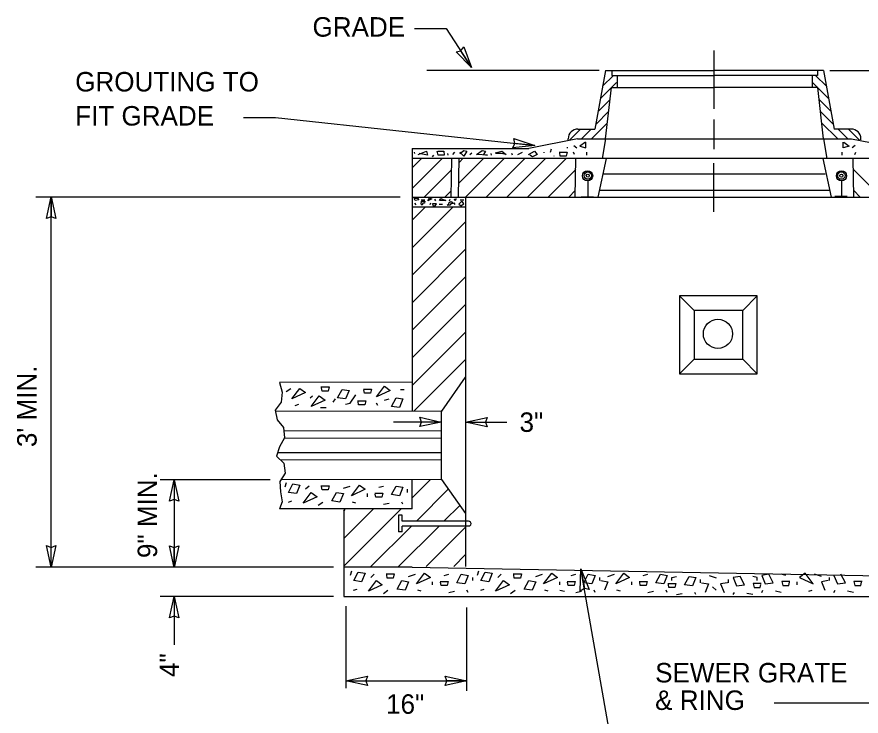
# Model space of a CAD drawing. Extents: x 19188 to 19495, y 20866 to 21061.
# Drawn here: x 19289.27 to 19325.6, y 20943.77 to 20973.85 of the extents above; entities that cross this region are included whole.
import ezdxf

# ---------------------------------------------------------------- set-up
doc = ezdxf.new("R2010")
doc.units = 0
doc.layers.add('G-ANNO-NOTE', color=7, linetype='Continuous')

msp = doc.modelspace()

# ---------------------------------------------------------------- linework, layer by layer
at = {"layer": 'G-ANNO-NOTE'}
for p, q in [((19306.374, 20973.354), (19307.75, 20973.354)), ((19307.75, 20973.354), (19308.836, 20971.674)), ((19308.836, 20971.674), (19308.373, 20972.39)), ((19314.326, 20971.541), (19306.915, 20971.541)), ((19314.6, 20971.541), (19314.141, 20969.028)), ((19314.476, 20970.865), (19314.943, 20971.332)), ((19314.6, 20971.541), (19319.291, 20971.541)), ((19314.867, 20971.541), (19314.867, 20971.332)), ((19314.867, 20971.332), (19319.291, 20971.332)), ((19315.098, 20971.332), (19315.098, 20970.822)), ((19323.983, 20971.541), (19319.291, 20971.541)), ((19323.715, 20971.332), (19319.291, 20971.332)), ((19323.484, 20971.332), (19323.484, 20970.822)), ((19324.107, 20970.865), (19323.639, 20971.332)), ((19323.715, 20971.541), (19323.715, 20971.332)), ((19323.983, 20971.541), (19324.442, 20969.028)), ((19324.256, 20971.541), (19342.735, 20971.541)), ((19314.404, 20970.358), (19315.077, 20971.03)), ((19324.178, 20970.358), (19323.506, 20971.03)), ((19314.6, 20968.603), (19314.855, 20970.808)), ((19314.855, 20970.808), (19319.291, 20970.808)), ((19323.728, 20970.808), (19319.291, 20970.808)), ((19323.983, 20968.603), (19323.728, 20970.808)), ((19314.278, 20969.777), (19314.793, 20970.293)), ((19324.305, 20969.777), (19323.789, 20970.293)), ((19299.023, 20969.523), (19300.399, 20969.523)), ((19300.399, 20969.523), (19311.551, 20968.313)), ((19314.734, 20969.785), (19314.19, 20969.242)), ((19323.849, 20969.785), (19324.392, 20969.242)), ((19314.004, 20968.615), (19314.673, 20969.284)), ((19324.579, 20968.615), (19323.91, 20969.284)), ((19313.054, 20968.554), (19313.528, 20969.028)), ((19313.414, 20969.028), (19314.141, 20969.028)), ((19313.574, 20968.625), (19313.962, 20969.014)), ((19325.169, 20969.028), (19324.442, 20969.028)), ((19325.009, 20968.625), (19324.62, 20969.014)), ((19325.528, 20968.554), (19325.054, 20969.028)), ((19311.551, 20968.313), (19310.704, 20968.405)), ((19313.398, 20968.609), (19311.304, 20968.19)), ((19312.995, 20968.564), (19312.995, 20968.609)), ((19313.398, 20968.609), (19325.184, 20968.609)), ((19314.6, 20968.603), (19314.453, 20967.766)), ((19323.983, 20968.603), (19324.129, 20967.766)), ((19325.184, 20968.609), (19327.279, 20968.19)), ((19325.588, 20968.564), (19325.588, 20968.609)), ((19306.277, 20968.19), (19306.277, 20956.881)), ((19306.277, 20968.19), (19311.304, 20968.19)), ((19306.277, 20967.771), (19332.306, 20967.771)), ((19306.277, 20966.462), (19307.585, 20967.771)), ((19306.277, 20967.351), (19306.697, 20967.771)), ((19307.952, 20966.096), (19307.986, 20967.764)), ((19308.267, 20966.119), (19308.3, 20967.766)), ((19309.363, 20967.771), (19308.294, 20966.703)), ((19308.474, 20967.771), (19308.311, 20967.608)), ((19308.575, 20966.096), (19310.221, 20967.741)), ((19309.464, 20966.096), (19311.116, 20967.747)), ((19312.029, 20967.771), (19310.371, 20966.114)), ((19311.242, 20966.096), (19312.918, 20967.771)), ((19313.295, 20966.096), (19313.328, 20967.771)), ((19314.633, 20967.766), (19314.274, 20966.098)), ((19323.95, 20967.766), (19324.309, 20966.098)), ((19325.288, 20966.096), (19325.254, 20967.771)), ((19312.13, 20966.096), (19313.318, 20967.284)), ((19326.452, 20966.096), (19325.264, 20967.284)), ((19306.798, 20966.096), (19307.965, 20967.262)), ((19314.504, 20967.098), (19324.055, 20967.098)), ((19313.836, 20966.798), (19313.836, 20966.118)), ((19324.747, 20966.798), (19324.747, 20966.118)), ((19307.687, 20966.096), (19307.958, 20966.366)), ((19313.019, 20966.096), (19313.3, 20966.377)), ((19314.376, 20966.39), (19324.252, 20966.39)), ((19319.274, 20966.39), (19319.274, 20966.39)), ((19319.308, 20966.39), (19319.308, 20966.39)), ((19325.563, 20966.096), (19325.282, 20966.377)), ((19305.758, 20966.096), (19290.082, 20966.096)), ((19290.747, 20950.176), (19290.747, 20966.106)), ((19290.747, 20966.106), (19290.747, 20965.254)), ((19306.277, 20966.096), (19332.306, 20966.096)), ((19306.361, 20966.044), (19306.503, 20966.058)), ((19306.402, 20965.948), (19306.361, 20966.044)), ((19306.57, 20965.975), (19306.402, 20965.948)), ((19306.503, 20966.058), (19306.57, 20965.975)), ((19306.663, 20965.797), (19306.688, 20965.921)), ((19306.67, 20965.986), (19306.818, 20965.986)), ((19306.688, 20965.921), (19306.822, 20965.921)), ((19306.738, 20965.838), (19306.712, 20965.756)), ((19306.813, 20965.838), (19306.738, 20965.838)), ((19306.822, 20965.921), (19306.813, 20965.838)), ((19306.948, 20965.934), (19307.023, 20966.058)), ((19307.124, 20966.03), (19306.948, 20965.934)), ((19307.023, 20966.058), (19307.124, 20966.03)), ((19307.451, 20965.948), (19307.518, 20966.044)), ((19307.728, 20965.948), (19307.451, 20965.948)), ((19307.518, 20966.044), (19307.728, 20965.948)), ((19307.862, 20965.811), (19307.87, 20965.866)), ((19307.87, 20965.866), (19307.946, 20965.907)), ((19307.963, 20965.825), (19307.896, 20965.756)), ((19307.946, 20965.907), (19308.022, 20965.88)), ((19308.039, 20965.825), (19307.963, 20965.825)), ((19308.022, 20965.88), (19308.039, 20965.825)), ((19308.105, 20966.016), (19308.173, 20966.03)), ((19308.13, 20965.934), (19308.105, 20966.016)), ((19308.173, 20966.03), (19308.13, 20965.934)), ((19308.424, 20965.921), (19308.29, 20965.797)), ((19308.348, 20965.986), (19308.496, 20965.986)), ((19308.382, 20965.729), (19308.508, 20965.825)), ((19308.508, 20965.825), (19308.424, 20965.921)), ((19308.58, 20966.096), (19308.58, 20950.208)), ((19313.552, 20966.107), (19314.079, 20966.107)), ((19324.997, 20966.118), (19324.47, 20966.118)), ((19306.277, 20965.677), (19308.58, 20965.677)), ((19306.277, 20963.922), (19308.024, 20965.669)), ((19306.277, 20965.107), (19306.822, 20965.652)), ((19306.712, 20965.756), (19306.663, 20965.797)), ((19307.325, 20965.811), (19307.158, 20965.811)), ((19307.158, 20965.811), (19307.174, 20965.742)), ((19307.174, 20965.742), (19307.275, 20965.729)), ((19307.275, 20965.729), (19307.325, 20965.811)), ((19307.442, 20965.794), (19307.59, 20965.794)), ((19307.779, 20965.756), (19307.862, 20965.811)), ((19307.854, 20965.756), (19307.779, 20965.756)), ((19307.896, 20965.756), (19307.854, 20965.756)), ((19308.29, 20965.797), (19308.382, 20965.729)), ((19306.277, 20962.737), (19308.579, 20965.039)), ((19306.277, 20961.552), (19308.577, 20963.852)), ((19306.277, 20960.367), (19308.575, 20962.665)), ((19321.131, 20961.851), (19317.78, 20961.851)), ((19317.78, 20961.851), (19317.78, 20958.499)), ((19317.78, 20961.851), (19318.408, 20961.222)), ((19321.131, 20961.851), (19320.503, 20961.222)), ((19321.131, 20958.499), (19321.131, 20961.851)), ((19306.277, 20959.182), (19308.572, 20961.478)), ((19318.408, 20961.222), (19318.408, 20959.127)), ((19320.503, 20961.222), (19318.408, 20961.222)), ((19320.503, 20959.127), (19320.503, 20961.222)), ((19306.277, 20957.997), (19308.571, 20960.291)), ((19306.346, 20956.881), (19308.568, 20959.104)), ((19318.408, 20959.127), (19317.78, 20958.499)), ((19318.408, 20959.127), (19320.503, 20959.127)), ((19320.503, 20959.127), (19321.131, 20958.499)), ((19308.567, 20958.349), (19307.54, 20956.881)), ((19317.78, 20958.499), (19321.131, 20958.499)), ((19306.277, 20958.136), (19300.565, 20958.127)), ((19300.857, 20957.732), (19301.054, 20957.87)), ((19301.103, 20957.412), (19301.447, 20957.87)), ((19301.447, 20957.87), (19301.694, 20957.686)), ((19303.073, 20957.458), (19303.27, 20957.824)), ((19303.27, 20957.824), (19303.566, 20957.778)), ((19304.748, 20957.504), (19305.092, 20957.961)), ((19305.092, 20957.961), (19305.339, 20957.778)), ((19305.782, 20957.824), (19305.929, 20957.824)), ((19301.694, 20957.686), (19301.103, 20957.412)), ((19301.891, 20957.458), (19301.989, 20957.55)), ((19301.94, 20957.092), (19302.285, 20957.55)), ((19302.285, 20957.55), (19302.531, 20957.366)), ((19303.418, 20957.412), (19303.073, 20957.458)), ((19303.566, 20957.778), (19303.418, 20957.412)), ((19303.615, 20957.229), (19303.861, 20957.595)), ((19305.339, 20957.778), (19304.748, 20957.504)), ((19305.388, 20957.092), (19305.585, 20957.458)), ((19305.585, 20957.458), (19305.88, 20957.412)), ((19301.25, 20957.138), (19301.398, 20957.184)), ((19302.531, 20957.366), (19301.94, 20957.092)), ((19302.876, 20957.275), (19302.975, 20957.412)), ((19303.418, 20957.184), (19303.615, 20957.229)), ((19304.797, 20957.138), (19304.748, 20957.229)), ((19305.092, 20957.366), (19305.29, 20957.412)), ((19305.88, 20957.412), (19305.733, 20957.047)), ((19307.54, 20956.881), (19300.415, 20956.869)), ((19302.334, 20957.047), (19302.581, 20957.047)), ((19305.733, 20957.047), (19305.388, 20957.092)), ((19307.531, 20956.881), (19307.561, 20956.912)), ((19307.533, 20956.881), (19307.533, 20953.949)), ((19307.533, 20956.42), (19305.48, 20956.42)), ((19307.533, 20956.42), (19306.681, 20956.42)), ((19308.58, 20956.42), (19310.36, 20956.42)), ((19308.58, 20956.42), (19309.434, 20956.42)), ((19307.541, 20956.043), (19300.787, 20956.032)), ((19307.519, 20955.729), (19300.787, 20955.718)), ((19307.519, 20955.101), (19300.505, 20955.089)), ((19307.519, 20954.787), (19300.637, 20954.775)), ((19300.167, 20953.937), (19295.44, 20953.937)), ((19296.039, 20953.937), (19296.039, 20950.166)), ((19296.039, 20953.937), (19296.039, 20953.084)), ((19307.545, 20953.949), (19300.638, 20953.937)), ((19306.277, 20952.69), (19306.277, 20953.949)), ((19306.277, 20953.153), (19307.072, 20953.949)), ((19307.545, 20953.949), (19308.577, 20952.484)), ((19300.857, 20953.801), (19300.808, 20953.618)), ((19300.955, 20953.389), (19301.152, 20953.755)), ((19301.152, 20953.755), (19301.447, 20953.709)), ((19301.447, 20953.709), (19301.3, 20953.343)), ((19301.842, 20953.663), (19301.694, 20953.527)), ((19303.319, 20953.572), (19303.615, 20953.663)), ((19303.664, 20953.252), (19304.009, 20953.709)), ((19304.255, 20953.527), (19303.664, 20953.252)), ((19304.009, 20953.709), (19304.255, 20953.527)), ((19304.846, 20953.618), (19305.043, 20953.663)), ((19305.388, 20953.298), (19305.585, 20953.663)), ((19305.585, 20953.663), (19305.88, 20953.618)), ((19305.88, 20953.618), (19305.733, 20953.252)), ((19306.078, 20953.389), (19306.078, 20953.527)), ((19307.834, 20953.526), (19306.482, 20952.174)), ((19301.3, 20953.343), (19300.955, 20953.389)), ((19301.596, 20952.932), (19301.94, 20953.389)), ((19302.186, 20953.206), (19301.596, 20952.932)), ((19301.94, 20953.389), (19302.186, 20953.206)), ((19302.827, 20953.024), (19303.024, 20953.389)), ((19303.024, 20953.389), (19303.319, 20953.343)), ((19303.319, 20953.343), (19303.171, 20952.978)), ((19304.354, 20953.206), (19304.354, 20953.343)), ((19305.733, 20953.252), (19305.388, 20953.298)), ((19300.955, 20952.978), (19301.103, 20953.024)), ((19302.236, 20952.841), (19302.433, 20952.978)), ((19303.171, 20952.978), (19302.827, 20953.024)), ((19303.861, 20952.932), (19303.713, 20952.978)), ((19305.043, 20952.886), (19305.29, 20952.932)), ((19305.88, 20952.886), (19305.831, 20952.978)), ((19308.328, 20952.834), (19307.664, 20952.171)), ((19306.277, 20952.69), (19300.574, 20952.68)), ((19303.344, 20950.22), (19305.807, 20952.683)), ((19303.344, 20951.405), (19304.605, 20952.666)), ((19303.344, 20952.591), (19303.403, 20952.65)), ((19303.344, 20952.649), (19303.344, 20950.176)), ((19305.849, 20952.411), (19305.694, 20952.411)), ((19305.694, 20952.411), (19305.694, 20951.693)), ((19305.849, 20952.156), (19305.849, 20952.411)), ((19308.697, 20952.156), (19305.849, 20952.156)), ((19304.492, 20950.184), (19306.25, 20951.942)), ((19305.684, 20950.191), (19307.426, 20951.932)), ((19305.849, 20951.693), (19305.694, 20951.693)), ((19308.701, 20951.947), (19305.849, 20951.947)), ((19305.849, 20951.693), (19305.849, 20951.947)), ((19306.876, 20950.198), (19308.578, 20951.899)), ((19290.747, 20950.176), (19290.747, 20951.029)), ((19296.039, 20950.166), (19296.039, 20951.018)), ((19308.068, 20950.205), (19308.58, 20950.717)), ((19302.896, 20950.176), (19290.082, 20950.176)), ((19306.277, 20950.176), (19303.344, 20950.176)), ((19303.344, 20950.176), (19303.344, 20948.92)), ((19303.664, 20950.006), (19303.615, 20949.824)), ((19303.763, 20949.595), (19303.959, 20949.961)), ((19303.959, 20949.961), (19304.255, 20949.915)), ((19304.255, 20949.915), (19304.107, 20949.549)), ((19304.649, 20949.869), (19304.501, 20949.732)), ((19306.127, 20949.778), (19306.422, 20949.869)), ((19306.277, 20950.176), (19330.133, 20949.734)), ((19306.471, 20949.458), (19306.816, 20949.915)), ((19306.816, 20949.915), (19307.063, 20949.732)), ((19307.653, 20949.824), (19307.851, 20949.869)), ((19308.195, 20949.504), (19308.392, 20949.869)), ((19308.392, 20949.869), (19308.688, 20949.824)), ((19309.131, 20950.006), (19309.082, 20949.824)), ((19309.229, 20949.595), (19309.426, 20949.961)), ((19309.426, 20949.961), (19309.722, 20949.915)), ((19309.722, 20949.915), (19309.574, 20949.549)), ((19310.116, 20949.869), (19309.968, 20949.732)), ((19311.594, 20949.778), (19311.889, 20949.869)), ((19311.938, 20949.458), (19312.283, 20949.915)), ((19312.283, 20949.915), (19312.53, 20949.732)), ((19313.12, 20949.824), (19313.318, 20949.869)), ((19315.064, 20941.426), (19313.543, 20950.097)), ((19313.543, 20950.097), (19313.691, 20949.257)), ((19313.662, 20949.504), (19313.859, 20949.869)), ((19313.859, 20949.869), (19314.155, 20949.824)), ((19314.697, 20949.778), (19314.992, 20949.869)), ((19315.042, 20949.458), (19315.386, 20949.915)), ((19315.386, 20949.915), (19315.632, 20949.732)), ((19316.224, 20949.824), (19316.42, 20949.869)), ((19316.765, 20949.504), (19316.962, 20949.869)), ((19316.962, 20949.869), (19317.258, 20949.824)), ((19321.621, 20949.869), (19321.325, 20949.824)), ((19321.818, 20949.504), (19321.621, 20949.869)), ((19322.359, 20949.824), (19322.162, 20949.869)), ((19323.196, 20949.915), (19322.95, 20949.732)), ((19323.541, 20949.458), (19323.196, 20949.915)), ((19323.886, 20949.778), (19323.59, 20949.869)), ((19324.92, 20949.504), (19324.723, 20949.869)), ((19304.107, 20949.549), (19303.763, 20949.595)), ((19304.403, 20949.138), (19304.748, 20949.595)), ((19304.748, 20949.595), (19304.994, 20949.412)), ((19305.634, 20949.229), (19305.831, 20949.595)), ((19305.831, 20949.595), (19306.127, 20949.549)), ((19306.127, 20949.549), (19305.979, 20949.184)), ((19307.063, 20949.732), (19306.471, 20949.458)), ((19307.161, 20949.412), (19307.161, 20949.549)), ((19308.54, 20949.458), (19308.195, 20949.504)), ((19308.688, 20949.824), (19308.54, 20949.458)), ((19308.885, 20949.595), (19308.885, 20949.732)), ((19309.574, 20949.549), (19309.229, 20949.595)), ((19309.87, 20949.138), (19310.215, 20949.595)), ((19310.215, 20949.595), (19310.461, 20949.412)), ((19311.101, 20949.229), (19311.298, 20949.595)), ((19311.298, 20949.595), (19311.594, 20949.549)), ((19311.594, 20949.549), (19311.446, 20949.184)), ((19312.53, 20949.732), (19311.938, 20949.458)), ((19312.628, 20949.412), (19312.628, 20949.549)), ((19314.007, 20949.458), (19313.662, 20949.504)), ((19314.155, 20949.824), (19314.007, 20949.458)), ((19314.352, 20949.595), (19314.352, 20949.732)), ((19314.401, 20949.595), (19314.697, 20949.549)), ((19314.697, 20949.549), (19314.549, 20949.184)), ((19315.632, 20949.732), (19315.042, 20949.458)), ((19315.731, 20949.412), (19315.731, 20949.549)), ((19317.11, 20949.458), (19316.765, 20949.504)), ((19317.258, 20949.824), (19317.11, 20949.458)), ((19317.455, 20949.732), (19317.652, 20949.778)), ((19317.455, 20949.595), (19317.455, 20949.732)), ((19317.997, 20949.412), (19318.194, 20949.778)), ((19318.194, 20949.778), (19318.489, 20949.732)), ((19318.489, 20949.732), (19318.341, 20949.366)), ((19318.686, 20949.504), (19318.686, 20949.641)), ((19318.736, 20949.504), (19319.031, 20949.458)), ((19319.368, 20949.709), (19319.072, 20949.8)), ((19319.848, 20949.504), (19319.552, 20949.458)), ((19319.897, 20949.504), (19319.897, 20949.641)), ((19320.389, 20949.778), (19320.093, 20949.732)), ((19320.093, 20949.732), (19320.241, 20949.366)), ((19320.586, 20949.412), (19320.389, 20949.778)), ((19321.128, 20949.732), (19320.931, 20949.778)), ((19321.128, 20949.595), (19321.128, 20949.732)), ((19321.325, 20949.824), (19321.473, 20949.458)), ((19321.473, 20949.458), (19321.818, 20949.504)), ((19322.852, 20949.412), (19322.852, 20949.549)), ((19322.95, 20949.732), (19323.541, 20949.458)), ((19324.181, 20949.595), (19323.886, 20949.549)), ((19323.886, 20949.549), (19324.034, 20949.184)), ((19324.231, 20949.595), (19324.231, 20949.732)), ((19324.428, 20949.824), (19324.576, 20949.458)), ((19324.576, 20949.458), (19324.92, 20949.504)), ((19303.762, 20949.184), (19303.91, 20949.23)), ((19304.994, 20949.412), (19304.403, 20949.138)), ((19305.043, 20949.046), (19305.24, 20949.184)), ((19305.979, 20949.184), (19305.634, 20949.229)), ((19306.668, 20949.138), (19306.521, 20949.184)), ((19307.851, 20949.092), (19308.097, 20949.138)), ((19308.688, 20949.092), (19308.638, 20949.184)), ((19309.229, 20949.184), (19309.377, 20949.23)), ((19310.461, 20949.412), (19309.87, 20949.138)), ((19310.51, 20949.046), (19310.707, 20949.184)), ((19311.446, 20949.184), (19311.101, 20949.229)), ((19312.135, 20949.138), (19311.988, 20949.184)), ((19312.828, 20949.131), (19312.631, 20949.177)), ((19313.318, 20949.092), (19313.564, 20949.138)), ((19314.155, 20949.092), (19314.106, 20949.184)), ((19315.239, 20949.138), (19315.091, 20949.184)), ((19316.42, 20949.092), (19316.667, 20949.138)), ((19317.258, 20949.092), (19317.209, 20949.184)), ((19318.341, 20949.366), (19317.997, 20949.412)), ((19319.031, 20949.458), (19318.883, 20949.092)), ((19319.209, 20949.326), (19319.357, 20949.189)), ((19319.552, 20949.458), (19319.699, 20949.092)), ((19320.241, 20949.366), (19320.586, 20949.412)), ((19321.325, 20949.092), (19321.374, 20949.184)), ((19322.162, 20949.092), (19321.916, 20949.138)), ((19323.344, 20949.138), (19323.492, 20949.184)), ((19324.428, 20949.092), (19324.477, 20949.184)), ((19325.265, 20949.092), (19325.018, 20949.138)), ((19302.896, 20948.92), (19295.44, 20948.92)), ((19296.039, 20948.92), (19296.039, 20946.829)), ((19296.039, 20948.92), (19296.039, 20948.067)), ((19303.344, 20948.92), (19337.906, 20948.92)), ((19317.652, 20949.001), (19317.898, 20949.046)), ((19318.489, 20949.001), (19318.44, 20949.092)), ((19320.094, 20949.001), (19320.143, 20949.092)), ((19320.931, 20949.001), (19320.685, 20949.046)), ((19303.428, 20948.497), (19303.428, 20944.975)), ((19308.621, 20948.435), (19308.621, 20944.852)), ((19303.428, 20945.284), (19308.621, 20945.284)), ((19303.428, 20945.284), (19304.282, 20945.284)), ((19308.621, 20945.284), (19307.768, 20945.284)), ((19321.853, 20944.333), (19326.959, 20944.333))]:
    msp.add_line(p, q, dxfattribs=at)
for points in [[(19308.373, 20972.39), (19308.503, 20972.564), (19308.836, 20971.674), (19308.17, 20972.346), (19308.373, 20972.39)], [(19319.263, 20972.407), (19319.263, 20969.893)], [(19319.263, 20969.435), (19319.263, 20968.156)], [(19310.704, 20968.405), (19310.651, 20968.616), (19311.551, 20968.313), (19310.61, 20968.219), (19310.704, 20968.405)], [(19313.735, 20968.461), (19313.497, 20968.285), (19313.757, 20968.214), (19313.757, 20968.461)], [(19324.847, 20968.461), (19325.086, 20968.285), (19324.826, 20968.214), (19324.826, 20968.461)], [(19306.36, 20968.038), (19306.381, 20967.968)], [(19306.533, 20967.932), (19306.901, 20968.073), (19306.945, 20967.897), (19306.577, 20967.968)], [(19307.379, 20968.073), (19307.639, 20968.073), (19307.661, 20967.897), (19307.401, 20967.897), (19307.357, 20968.073)], [(19308.03, 20967.932), (19308.116, 20968.038)], [(19308.333, 20967.968), (19308.507, 20968.108), (19308.637, 20968.073), (19308.507, 20967.861), (19308.333, 20968.038)], [(19308.767, 20967.932), (19308.854, 20968.003)], [(19309.049, 20967.932), (19309.288, 20968.108), (19309.44, 20968.073), (19309.353, 20967.932), (19309.526, 20967.897), (19309.071, 20967.932)], [(19309.852, 20968.003), (19310.134, 20968.073), (19310.329, 20967.932), (19310.112, 20967.968), (19309.874, 20967.968)], [(19310.828, 20967.932), (19311.023, 20968.038)], [(19311.284, 20967.932), (19311.544, 20968.073), (19311.653, 20967.932), (19311.457, 20967.826), (19311.349, 20967.897)], [(19311.956, 20968.003), (19311.956, 20968.038)], [(19312.238, 20968.038), (19312.282, 20968.179)], [(19312.607, 20968.038), (19312.954, 20968.038), (19312.911, 20967.861), (19312.65, 20967.861), (19312.629, 20968.003)], [(19312.976, 20968.214), (19312.933, 20968.214)], [(19313.258, 20967.932), (19313.215, 20968.038)], [(19313.236, 20968.32), (19313.367, 20968.214)], [(19313.8, 20967.897), (19313.8, 20968.038)], [(19324.782, 20967.897), (19324.782, 20968.038)], [(19325.346, 20968.32), (19325.216, 20968.214)], [(19325.324, 20967.932), (19325.368, 20968.038)], [(19307.162, 20967.826), (19307.206, 20967.897)], [(19307.834, 20967.897), (19307.813, 20967.968)], [(19309.7, 20967.897), (19309.678, 20967.968)], [(19310.59, 20967.897), (19310.568, 20967.968)], [(19312.39, 20967.861), (19312.369, 20967.861)], [(19319.263, 20965.458), (19319.263, 20967.561)], [(19290.747, 20965.254), (19290.544, 20965.179), (19290.747, 20966.106), (19290.942, 20965.181), (19290.747, 20965.254)], [(19306.445, 20965.764), (19306.401, 20965.834)], [(19307.06, 20965.775), (19307.081, 20965.845)], [(19307.292, 20965.942), (19307.249, 20966.013)], [(19307.89, 20965.939), (19307.912, 20966.01)], [(19308.131, 20965.777), (19308.088, 20965.848)], [(19300.565, 20958.127), (19300.683, 20957.704), (19300.639, 20957.269), (19300.386, 20956.93), (19300.475, 20956.519), (19300.743, 20956.18), (19300.787, 20955.745), (19300.565, 20955.358), (19300.446, 20954.946), (19300.758, 20954.656), (19300.817, 20954.221), (19300.579, 20953.858), (19300.609, 20953.423), (19300.683, 20952.988), (19300.574, 20952.68)], [(19302.357, 20957.929), (19302.705, 20957.929), (19302.662, 20957.753), (19302.401, 20957.753), (19302.379, 20957.894)], [(19304.18, 20957.838), (19304.527, 20957.838), (19304.484, 20957.662), (19304.224, 20957.662), (19304.201, 20957.803)], [(19303.934, 20957.335), (19304.281, 20957.335), (19304.237, 20957.159), (19303.977, 20957.159), (19303.955, 20957.3)], [(19306.681, 20956.42), (19306.606, 20956.624), (19307.533, 20956.42), (19306.608, 20956.226), (19306.681, 20956.42)], [(19309.434, 20956.42), (19309.508, 20956.216), (19308.58, 20956.42), (19309.507, 20956.615), (19309.434, 20956.42)], [(19296.039, 20953.084), (19295.836, 20953.009), (19296.039, 20953.937), (19296.234, 20953.011), (19296.039, 20953.084)], [(19302.357, 20953.678), (19302.705, 20953.678), (19302.662, 20953.501), (19302.401, 20953.501), (19302.379, 20953.643)], [(19304.673, 20953.358), (19305.02, 20953.358), (19304.976, 20953.182), (19304.716, 20953.182), (19304.694, 20953.323)], [(19290.747, 20951.029), (19290.951, 20951.104), (19290.747, 20950.176), (19290.553, 20951.102), (19290.747, 20951.029)], [(19296.039, 20951.018), (19296.243, 20951.093), (19296.039, 20950.166), (19295.845, 20951.091), (19296.039, 20951.018)], [(19305.165, 20949.884), (19305.512, 20949.884), (19305.469, 20949.707), (19305.209, 20949.707), (19305.187, 20949.848)], [(19310.632, 20949.884), (19310.979, 20949.884), (19310.936, 20949.707), (19310.676, 20949.707), (19310.654, 20949.848)], [(19313.691, 20949.257), (19313.503, 20949.148), (19313.543, 20950.097), (19313.895, 20949.219), (19313.691, 20949.257)], [(19307.48, 20949.563), (19307.827, 20949.563), (19307.783, 20949.387), (19307.523, 20949.387), (19307.502, 20949.528)], [(19312.947, 20949.563), (19313.294, 20949.563), (19313.251, 20949.387), (19312.99, 20949.387), (19312.969, 20949.528)], [(19316.05, 20949.563), (19316.397, 20949.563), (19316.354, 20949.387), (19316.094, 20949.387), (19316.072, 20949.528)], [(19317.281, 20949.472), (19317.629, 20949.472), (19317.585, 20949.296), (19317.325, 20949.296), (19317.303, 20949.437)], [(19321.301, 20949.472), (19320.955, 20949.472), (19320.998, 20949.296), (19321.258, 20949.296), (19321.28, 20949.437)], [(19322.533, 20949.563), (19322.186, 20949.563), (19322.229, 20949.387), (19322.489, 20949.387), (19322.511, 20949.528)], [(19325.636, 20949.563), (19325.288, 20949.563), (19325.332, 20949.387), (19325.592, 20949.387), (19325.614, 20949.528)], [(19296.039, 20948.066), (19295.836, 20947.992), (19296.039, 20948.92), (19296.234, 20947.994), (19296.039, 20948.066)], [(19304.282, 20945.284), (19304.356, 20945.081), (19303.428, 20945.284), (19304.354, 20945.479), (19304.282, 20945.284)], [(19307.768, 20945.284), (19307.693, 20945.488), (19308.621, 20945.284), (19307.695, 20945.09), (19307.768, 20945.284)]]:
    msp.add_lwpolyline(points, dxfattribs=at)
for centre, radius in [((19313.829, 20967.016), 0.22), ((19313.836, 20967.022), 0.157), ((19313.836, 20967.022), 0.0628), ((19324.753, 20967.016), 0.22), ((19324.747, 20967.022), 0.157), ((19324.747, 20967.022), 0.0628), ((19319.437, 20960.215), 0.628)]:
    msp.add_circle(centre, radius, dxfattribs=at)
for centre, radius, start, end in [((19313.414, 20968.609), 0.419, 90, 180), ((19325.169, 20968.609), 0.419, 0, 90), ((19308.708, 20952.052), 0.105, 266.522, 96.1025)]:
    msp.add_arc(centre, radius, start, end, dxfattribs=at)

# ---------------------------------------------------------------- texts
for s, height, p in [('GRADE', 0.8379, (19301.992, 20973.003)), ('GROUTING TO', 0.83785, (19291.781, 20970.644)), ('FIT GRADE', 0.8379, (19291.781, 20969.177)), ('3"', 0.8379, (19310.9, 20955.996)), ('SEWER GRATE', 0.83785, (19316.735, 20945.216)), ('& RING', 0.8379, (19316.735, 20944.033)), ('16"', 0.8379, (19305.157, 20943.867))]:
    msp.add_text(s, height=height, dxfattribs=at).set_placement(p)
for s, p in [("3' MIN.", (19290.122, 20955.34)), ('9" MIN.', (19295.306, 20950.567)), ('4"', (19296.247, 20945.45))]:
    msp.add_text(s, height=0.8379, rotation=90, dxfattribs=at).set_placement(p)

doc.saveas('drawing.dxf')
